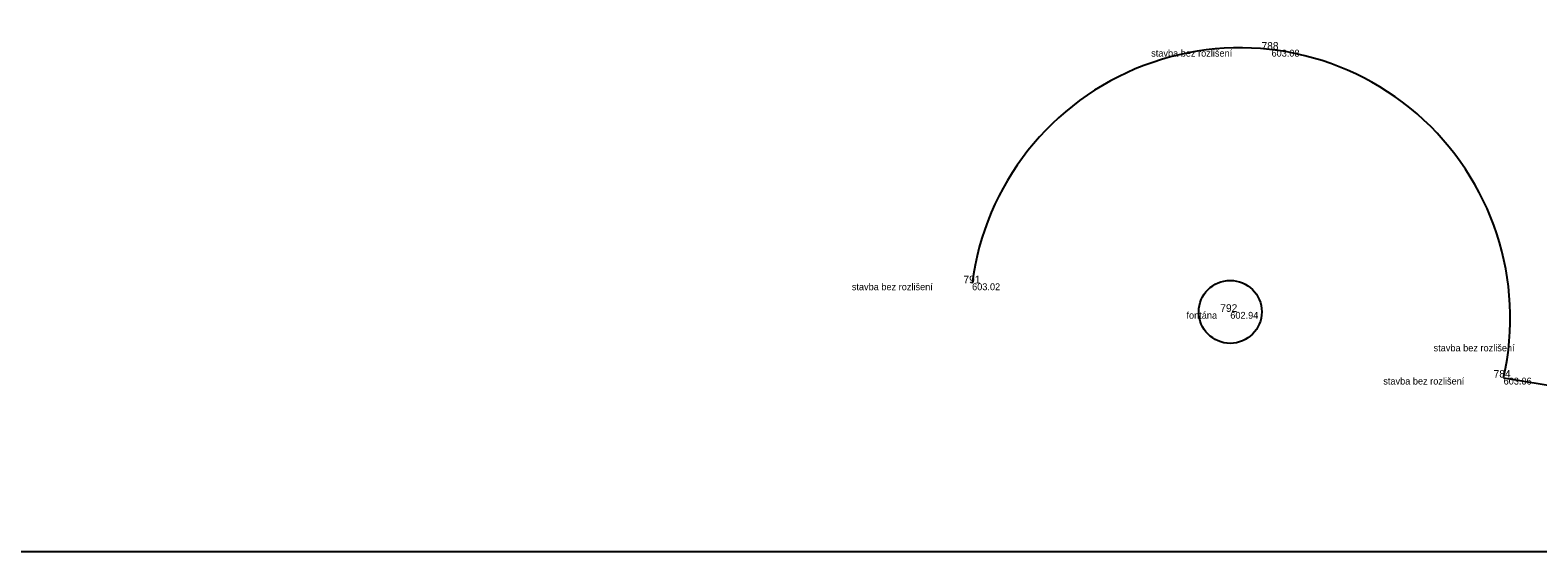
# Model space of a CAD drawing. Extents: x -866441 to -866144, y -1037389 to -1036968.
# Drawn here: x -866398.85 to -866379.07, y -1037283.73 to -1037276.89 of the extents above; entities that cross this region are included whole.
import ezdxf

# ---------------------------------------------------------------- set-up
doc = ezdxf.new("R2010")
doc.units = 0
for name, color, linetype in [('32 stavba bez rozlišení', 7, 'Continuous'), ('Bod', 7, 'Continuous'), ('Bod_popis', 7, 'Continuous'), ('Bod_výška', 7, 'Continuous'), ('Bod_číslo', 7, 'Continuous'), ('Fontána', 7, 'Continuous'), ('Formát', 7, 'Continuous')]:
    doc.layers.add(name, color=color, linetype=linetype)

msp = doc.modelspace()

# ---------------------------------------------------------------- linework, layer by layer
at = {"layer": '32 stavba bez rozlišení'}
msp.add_lwpolyline([(-866379.515, -1037281.448), (-866375.403, -1037282.124), (-866375.334, -1037281.733), (-866375.305, -1037281.568)], dxfattribs=at)
msp.add_ellipse((-866382.974, -1037280.668), major_axis=(-2.833, 2.133), ratio=0.999922, start_param=3.565341, end_param=6.799248, dxfattribs=at)
at = {"layer": 'Bod'}
for p, q in [((-866382.561, -1037277.147), (-866382.561, -1037277.147)), ((-866386.49, -1037280.211), (-866386.49, -1037280.211)), ((-866383.102, -1037280.585), (-866383.102, -1037280.585)), ((-866379.515, -1037281.448), (-866379.515, -1037281.448))]:
    msp.add_line(p, q, dxfattribs=at)
at = {"layer": 'Fontána'}
msp.add_circle((-866383.102, -1037280.585), 0.413, dxfattribs=at)
at = {"layer": 'Formát'}
msp.add_line((-866143.782, -1037283.732), (-866440.782, -1037283.732), dxfattribs=at)

# ---------------------------------------------------------------- texts
at = {"layer": 'Bod_popis'}
for s, p in [('stavba bez rozlišení', (-866384.14, -1037277.237)), ('stavba bez rozlišení', (-866388.069, -1037280.301)), ('fontána', (-866383.677, -1037280.675)), ('stavba bez rozlišení', (-866380.434, -1037281.103)), ('stavba bez rozlišení', (-866381.094, -1037281.538))]:
    msp.add_text(s, height=0.09, dxfattribs=at).set_placement(p)
at = {"layer": 'Bod_výška'}
for s, p in [('603.08', (-866382.561, -1037277.237)), ('603.02', (-866386.49, -1037280.301)), ('602.94', (-866383.102, -1037280.675)), ('603.06', (-866379.515, -1037281.538))]:
    msp.add_text(s, height=0.09, dxfattribs=at).set_placement(p)
at = {"layer": 'Bod_číslo'}
for s, p in [('788', (-866382.692, -1037277.147)), ('791', (-866386.604, -1037280.211)), ('792', (-866383.233, -1037280.585)), ('784', (-866379.646, -1037281.448))]:
    msp.add_text(s, height=0.1, dxfattribs=at).set_placement(p)

doc.saveas('drawing.dxf')
